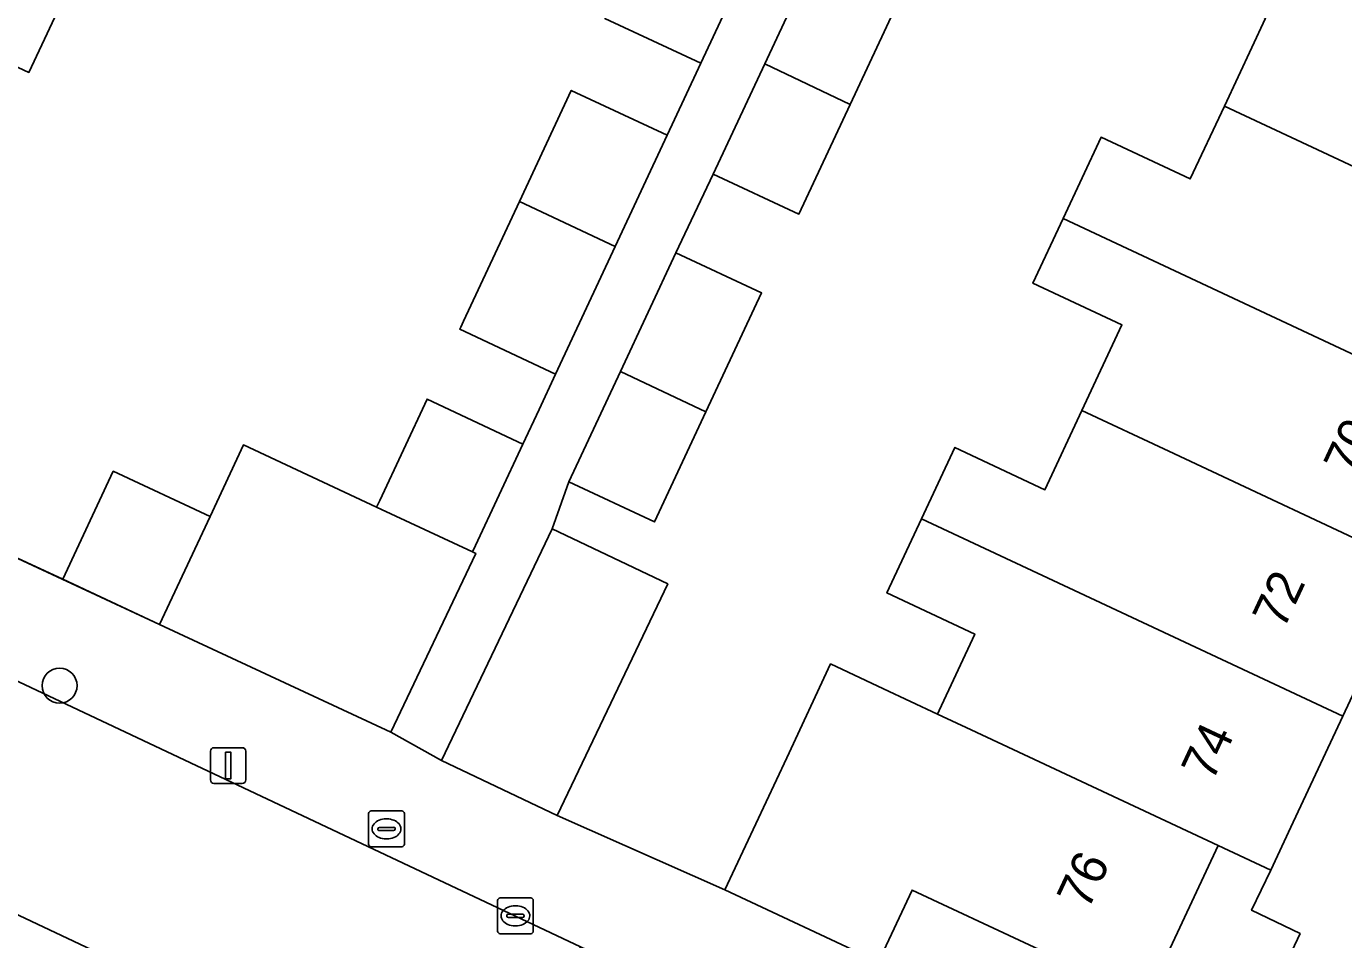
# Model space of a CAD drawing. Extents: x 159817 to 160765, y 380688 to 381638.
# Drawn here: x 160139.34 to 160176.21, y 381297.06 to 381322.59 of the extents above; entities that cross this region are included whole.
import ezdxf

# ---------------------------------------------------------------- set-up
doc = ezdxf.new("R2010")
doc.units = 0
for name, color, linetype in [('IMGEO_Boom', 7, 'Continuous'), ('IMGEO_Erf', 7, 'Continuous'), ('IMGEO_Kolk', 7, 'Continuous'), ('IMGEO_Lichtmast', 7, 'Continuous'), ('IMGEO_Muur', 7, 'Continuous'), ('IMGEO_Pand', 7, 'Continuous'), ('IMGEO_Pand_nummerreeks', 7, 'Continuous'), ('IMGEO_Rijbaan_lokaal_open', 7, 'Continuous'), ('IMGEO_Rioolput', 7, 'Continuous'), ('IMGEO_Voetpad_halfverhard', 7, 'Continuous'), ('IMGEO_Voetpad_open', 7, 'Continuous')]:
    doc.layers.add(name, color=color, linetype=linetype)

msp = doc.modelspace()

# ---------------------------------------------------------------- linework, layer by layer
at = {"layer": 'IMGEO_Boom'}
msp.add_circle((160140.273, 381304.158), 0.489, dxfattribs=at)
at = {"layer": 'IMGEO_Erf'}
for points in [[(160140.503, 381323.628), (160139.414, 381321.305), (160134.252, 381323.726)], [(160163.89, 381323.6), (160162.395, 381320.404), (160160.962, 381317.341), (160158.566, 381318.462), (160157.686, 381316.612), (160157.52, 381316.258), (160159.917, 381315.137), (160158.362, 381311.814), (160156.922, 381308.737), (160154.526, 381309.858), (160154.06, 381308.546), (160157.292, 381307.002), (160154.197, 381300.523), (160158.89, 381298.445), (160160.62, 381302.142), (160161.847, 381304.765), (160163.331, 381304.071), (160164.838, 381303.365), (160164.883, 381303.461), (160165.883, 381305.599), (160163.423, 381306.75), (160164.394, 381308.825), (160165.326, 381310.817), (160167.848, 381309.637), (160168.883, 381311.848), (160170.003, 381314.242), (160167.509, 381315.409), (160168.355, 381317.216), (160169.419, 381319.491), (160171.913, 381318.324), (160172.867, 381320.363), (160174.016, 381322.82)], [(160134.175, 381309.996), (160140.363, 381307.133), (160141.774, 381310.153), (160144.484, 381308.888), (160145.42, 381310.891), (160149.146, 381309.151), (160149.232, 381309.335), (160150.557, 381312.17), (160153.237, 381310.913), (160153.69, 381311.881), (160154.15, 381312.865), (160151.47, 381314.123), (160151.498, 381314.184), (160151.576, 381314.351), (160153.14, 381317.696), (160154.591, 381320.8), (160157.273, 381319.547), (160157.75, 381320.567), (160158.215, 381321.562), (160155.533, 381322.815)]]:
    msp.add_lwpolyline(points, dxfattribs=at)
msp.add_lwpolyline([(160174.168, 381298.997), (160172.69, 381299.689), (160170.675, 381295.381), (160164.129, 381298.444), (160163.189, 381296.434), (160171.277, 381292.584), (160173.102, 381293.237), (160174.985, 381297.226), (160173.629, 381297.876)], close=True, dxfattribs=at)
at = {"layer": 'IMGEO_Kolk'}
for p, q in [((160152.529, 381297.296), (160152.529, 381298.148)), ((160152.604, 381298.222), (160153.456, 381298.222)), ((160153.017, 381298.002), (160153.042, 381298.002)), ((160153.53, 381298.148), (160153.53, 381297.296)), ((160152.788, 381297.716), (160152.788, 381297.728)), ((160153.226, 381297.679), (160152.828, 381297.679)), ((160152.831, 381297.765), (160153.229, 381297.765)), ((160153.272, 381297.728), (160153.272, 381297.716)), ((160153.04, 381297.442), (160153.015, 381297.442)), ((160153.456, 381297.222), (160152.604, 381297.222))]:
    msp.add_line(p, q, dxfattribs=at)
for points in [[(160152.529, 381297.296), (160152.529, 381298.148)], [(160152.604, 381298.222), (160153.456, 381298.222)], [(160153.53, 381298.148), (160153.53, 381297.296)], [(160153.456, 381297.222), (160152.604, 381297.222)]]:
    msp.add_lwpolyline(points, dxfattribs=at)
for centre, radius, start, end in [((160152.606, 381298.146), 0.0765, 91.552, 178.448), ((160152.606, 381298.146), 0.0765, 91.552, 178.448), ((160153.454, 381298.146), 0.0765, 1.552, 88.448), ((160153.454, 381298.146), 0.0765, 1.552, 88.448), ((160152.828, 381297.725), 0.0403, 85.8775, 175.7526), ((160152.825, 381297.715), 0.0366, 178.938, 274.7102), ((160153.229, 381297.722), 0.043, 264.8664, 352.4533), ((160153.233, 381297.727), 0.0386, 1.7309, 96.639), ((160152.606, 381297.298), 0.0765, 181.552, 268.448), ((160152.606, 381297.298), 0.0765, 181.552, 268.448), ((160153.454, 381297.298), 0.0765, 271.552, 358.448), ((160153.454, 381297.298), 0.0765, 271.552, 358.448)]:
    msp.add_arc(centre, radius, start, end, dxfattribs=at)
for centre, major_axis, ratio, start_param, end_param in [((160153.016, 381297.722), (-0.387, 0.002), 0.722429, 4.712389, 7.853982), ((160153.041, 381297.722), (-0.39, 0.002), 0.717154, 1.570796, 4.712389)]:
    msp.add_ellipse(centre, major_axis=major_axis, ratio=ratio, start_param=start_param, end_param=end_param, dxfattribs=at)
at = {"layer": 'IMGEO_Lichtmast'}
for p, q in [((160144.594, 381302.423), (160145.384, 381302.423)), ((160145.384, 381302.423), (160144.594, 381302.423)), ((160144.494, 381301.523), (160144.494, 381302.323)), ((160144.494, 381302.323), (160144.494, 381301.523)), ((160145.484, 381302.323), (160145.484, 381301.523)), ((160145.484, 381301.523), (160145.484, 381302.323)), ((160145.384, 381301.423), (160144.594, 381301.423)), ((160144.594, 381301.423), (160145.384, 381301.423))]:
    msp.add_line(p, q, dxfattribs=at)
msp.add_lwpolyline([(160144.914, 381302.298), (160145.064, 381302.298), (160145.064, 381301.548), (160144.914, 381301.548), (160144.914, 381302.298)], dxfattribs=at)
for centre, start, end in [((160144.594, 381302.323), 90, 180), ((160144.594, 381302.323), 90, 180), ((160145.384, 381302.323), 0, 90), ((160145.384, 381302.323), 360, 90), ((160144.594, 381301.523), 180, 270), ((160144.594, 381301.523), 180, 270), ((160145.384, 381301.523), 270, 0), ((160145.384, 381301.523), 270, 0)]:
    msp.add_arc(centre, 0.1, start, end, dxfattribs=at)
at = {"layer": 'IMGEO_Muur'}
for points in [[(160132.009, 381311.009), (160143.074, 381305.87)], [(160154.197, 381300.523), (160158.89, 381298.445)]]:
    msp.add_lwpolyline(points, dxfattribs=at)
at = {"layer": 'IMGEO_Pand'}
for points in [[(160133.205, 381321.494), (160134.252, 381323.726), (160139.414, 381321.305), (160140.503, 381323.628), (160128.506, 381329.259), (160126.482, 381324.943), (160126.367, 381324.703)], [(160159.736, 381324.815), (160157.056, 381326.073), (160155.533, 381322.815), (160158.215, 381321.562)], [(160185.534, 381319.826), (160173.791, 381325.318), (160172.873, 381323.355), (160174.016, 381322.82), (160172.867, 381320.363), (160175.321, 381319.214), (160182.134, 381316.022), (160183.463, 381315.401)], [(160163.89, 381323.6), (160161.494, 381324.721), (160160.009, 381321.546), (160162.395, 381320.404)], [(160162.395, 381320.404), (160160.009, 381321.546), (160158.566, 381318.462), (160160.962, 381317.341)], [(160157.273, 381319.547), (160154.591, 381320.8), (160153.14, 381317.696), (160155.82, 381316.439)], [(160180.118, 381311.714), (160182.134, 381316.022), (160175.321, 381319.214), (160172.867, 381320.363), (160171.913, 381318.324), (160169.419, 381319.491), (160168.355, 381317.216)], [(160155.82, 381316.439), (160153.14, 381317.696), (160151.576, 381314.351), (160151.498, 381314.184), (160151.47, 381314.123), (160154.15, 381312.865)], [(160180.118, 381311.714), (160168.355, 381317.216), (160167.509, 381315.409), (160170.003, 381314.242), (160168.883, 381311.848), (160171.315, 381310.71), (160178.152, 381307.511)], [(160159.917, 381315.137), (160157.52, 381316.258), (160155.969, 381312.942), (160158.362, 381311.814)], [(160155.969, 381312.942), (160154.526, 381309.858), (160156.922, 381308.737), (160158.362, 381311.814)], [(160153.237, 381310.913), (160150.557, 381312.17), (160149.232, 381309.335), (160149.146, 381309.151), (160151.828, 381307.899), (160151.913, 381308.081)], [(160178.152, 381307.511), (160171.315, 381310.71), (160168.883, 381311.848), (160167.848, 381309.637), (160165.326, 381310.817), (160164.394, 381308.825), (160176.186, 381303.309)], [(160151.919, 381307.856), (160151.828, 381307.899), (160149.146, 381309.151), (160145.42, 381310.891), (160144.484, 381308.888), (160143.074, 381305.87), (160149.54, 381302.858)], [(160144.484, 381308.888), (160141.774, 381310.153), (160140.363, 381307.133), (160143.074, 381305.87)], [(160176.186, 381303.309), (160164.394, 381308.825), (160163.423, 381306.75), (160165.883, 381305.599), (160164.883, 381303.461), (160164.838, 381303.365), (160165.782, 381302.923), (160172.69, 381299.689), (160174.168, 381298.997), (160174.73, 381300.197)], [(160154.197, 381300.523), (160157.292, 381307.002), (160154.06, 381308.546), (160150.965, 381302.067)], [(160172.69, 381299.689), (160165.782, 381302.923), (160164.838, 381303.365), (160163.331, 381304.071), (160161.847, 381304.765), (160160.62, 381302.142), (160158.89, 381298.445), (160163.189, 381296.434), (160164.129, 381298.444), (160170.675, 381295.381)]]:
    msp.add_lwpolyline(points, close=True, dxfattribs=at)
at = {"layer": 'IMGEO_Rijbaan_lokaal_open'}
msp.add_lwpolyline([(160152.329, 381291.507), (160154.847, 381296.851), (160136.316, 381305.589), (160127.049, 381309.893), (160119.316, 381313.59), (160118.56, 381313.936), (160116.065, 381308.517), (160125.272, 381304.276)], close=True, dxfattribs=at)
at = {"layer": 'IMGEO_Rioolput'}
for p, q in [((160148.921, 381299.727), (160148.921, 381300.579)), ((160148.996, 381300.653), (160149.848, 381300.653)), ((160149.922, 381300.579), (160149.922, 381299.727)), ((160149.409, 381300.433), (160149.434, 381300.433)), ((160149.18, 381300.147), (160149.18, 381300.159)), ((160149.618, 381300.11), (160149.22, 381300.11)), ((160149.223, 381300.196), (160149.621, 381300.196)), ((160149.432, 381299.873), (160149.407, 381299.873)), ((160149.664, 381300.159), (160149.664, 381300.147)), ((160149.848, 381299.653), (160148.996, 381299.653))]:
    msp.add_line(p, q, dxfattribs=at)
for points in [[(160148.921, 381299.727), (160148.921, 381300.579)], [(160148.996, 381300.653), (160149.848, 381300.653)], [(160149.922, 381300.579), (160149.922, 381299.727)], [(160149.848, 381299.653), (160148.996, 381299.653)]]:
    msp.add_lwpolyline(points, dxfattribs=at)
for centre, radius, start, end in [((160148.998, 381300.577), 0.0765, 91.552, 178.448), ((160148.998, 381300.577), 0.0765, 91.552, 178.448), ((160149.846, 381300.577), 0.0765, 1.552, 88.448), ((160149.846, 381300.577), 0.0765, 1.552, 88.448), ((160149.22, 381300.156), 0.0403, 85.8775, 175.7526), ((160149.217, 381300.146), 0.0366, 178.938, 274.7102), ((160149.621, 381300.153), 0.043, 264.8664, 352.4533), ((160149.625, 381300.158), 0.0386, 1.7309, 96.639), ((160148.998, 381299.729), 0.0765, 181.552, 268.448), ((160148.998, 381299.729), 0.0765, 181.552, 268.448), ((160149.846, 381299.729), 0.0765, 271.552, 358.448), ((160149.846, 381299.729), 0.0765, 271.552, 358.448)]:
    msp.add_arc(centre, radius, start, end, dxfattribs=at)
for centre, major_axis, ratio, start_param, end_param in [((160149.408, 381300.153), (-0.387, 0.002), 0.722429, 4.712389, 7.853982), ((160149.433, 381300.153), (-0.39, 0.002), 0.717154, 1.570796, 4.712389)]:
    msp.add_ellipse(centre, major_axis=major_axis, ratio=ratio, start_param=start_param, end_param=end_param, dxfattribs=at)
at = {"layer": 'IMGEO_Voetpad_halfverhard'}
msp.add_lwpolyline([(160159.736, 381324.815), (160158.215, 381321.562), (160157.75, 381320.567), (160157.273, 381319.547), (160155.82, 381316.439), (160154.15, 381312.865), (160153.69, 381311.881), (160153.237, 381310.913), (160151.913, 381308.081), (160151.828, 381307.899), (160151.919, 381307.856), (160149.54, 381302.858), (160150.965, 381302.067), (160154.06, 381308.546), (160154.526, 381309.858), (160155.969, 381312.942), (160157.52, 381316.258), (160157.686, 381316.612), (160158.566, 381318.462), (160160.009, 381321.546), (160161.494, 381324.721)], dxfattribs=at)
at = {"layer": 'IMGEO_Voetpad_open'}
for points in [[(160187.554, 381324.142), (160185.534, 381319.826), (160183.463, 381315.401), (160182.134, 381316.022), (160180.118, 381311.714), (160178.152, 381307.511), (160176.186, 381303.309), (160174.73, 381300.197), (160174.168, 381298.997), (160173.629, 381297.876), (160174.985, 381297.226), (160173.102, 381293.237), (160171.277, 381292.584), (160175.381, 381290.671)], [(160149.54, 381302.858), (160143.074, 381305.87), (160140.363, 381307.133), (160134.175, 381309.996), (160132.009, 381311.009), (160121.655, 381315.852), (160118.127, 381317.544), (160118.21, 381314.096), (160118.56, 381313.936), (160119.316, 381313.59), (160127.049, 381309.893), (160136.316, 381305.589), (160154.847, 381296.851), (160157.307, 381295.691), (160168.726, 381290.362), (160169.633, 381289.895), (160170.37, 381289.569)], [(160168.179, 381284.054), (160167.131, 381284.615), (160165.662, 381285.327), (160154.789, 381290.347), (160152.329, 381291.507), (160125.272, 381304.276)], [(160175.381, 381290.671), (160171.277, 381292.584), (160163.189, 381296.434), (160158.89, 381298.445), (160154.197, 381300.523), (160150.965, 381302.067), (160149.54, 381302.858)]]:
    msp.add_lwpolyline(points, dxfattribs=at)

# ---------------------------------------------------------------- texts
at = {"layer": 'IMGEO_Pand_nummerreeks'}
for s, rotation, p in [('70', 64.9251, (160176.515, 381309.961)), ('72', 64.9251, (160174.522, 381305.698)), ('74', 64.9276, (160172.531, 381301.444)), ('76', 64.9333, (160169.05, 381297.854))]:
    msp.add_text(s, height=1, rotation=rotation, dxfattribs=at).set_placement(p)

doc.saveas('drawing.dxf')
